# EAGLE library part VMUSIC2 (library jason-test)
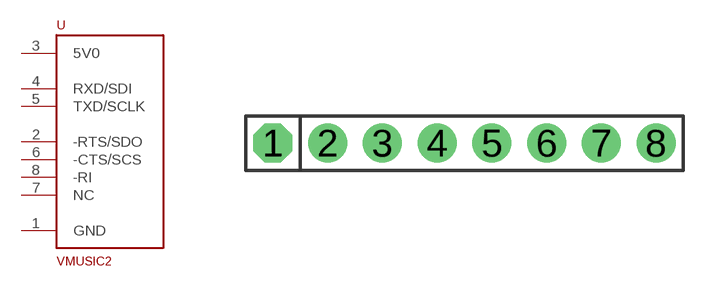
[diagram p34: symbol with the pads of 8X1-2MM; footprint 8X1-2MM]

Designator prefix -

## VMUSIC2  [8X1-2MM]
1  GND  pwr
2  -RTS/SDO
3  5V0  pwr
4  RXD/SDI
5  TXD/SCLK
6  -CTS/SCS
7  NC
8  -RI

## Footprint 8X1-2MM (pad centres in mm)
drill 0.8 pad 1.422 octagon: 1 -7,0
drill 0.8 pad 1.422 round: 2 -5,0; 3 -3,0; 4 -1,0; 5 1,0; 6 3,0; 7 5,0; 8 7,0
